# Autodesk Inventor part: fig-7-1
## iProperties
Created: 2004-05
Part Number: fig-7-1
Document SubType Name: Modeling
Designer: CADCIM Technologies
Manufacturer: Standard
Standards Organization: Custom
Density: 1 g/cm^3
Author: CADCIM Technologies
